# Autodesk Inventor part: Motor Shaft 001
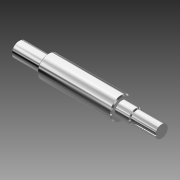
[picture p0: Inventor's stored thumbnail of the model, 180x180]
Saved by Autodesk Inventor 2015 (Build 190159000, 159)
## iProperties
Created: 2007-02
Part Number: Motor Shaft 001
Material: Steel
Document SubType Name: Modeling
Designer: Autodesk, Inc.
Density: 7.85 g/cm^3
Mass: 5212.32 g
Surface Area: 583.464 cm^2
Volume: 663.99 cm^3
Appearance: Chrome - Polished
CustomPartVersion: 1
Author: Autodesk, Inc.
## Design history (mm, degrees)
sketch "Main Sketch"
  geometry: L1 (0, 0)-(368.3, 0) reference; L2 (0, 0)-(0, 19.05); L3 (0, 19.05)-(76.2, 19.05); L4 (76.2, 19.05)-(76.2, 28.575); L5 (266.7, 28.575)-(266.7, 18.415); L6 (76.2, 28.575)-(266.7, 28.575); L7 (304.8, 18.415)-(304.8, 15.875); L8 (266.7, 18.415)-(304.8, 18.415); L9 (368.3, 15.875)-(368.3, 0); L10 (304.8, 15.875)-(368.3, 15.875)
  constraints: 20 end point, 5 vertical, 2 horizontal
  dimensions: "d3" = 38.1 diameter of L3 L1 (derived); "d4" = 57.15 diameter of L6 L1 (derived); "d10" = 36.83 diameter of L8 L1 (derived); "d20" = 31.75 diameter of L10 L1 (derived)
revolve "Revolution1" sketch "Main Sketch" stored, may be unused: angle "d5" = 0 deg
chamfer "Chamfer5" distance "d21" = 2.54; stored, may be unused: second distance "d22" = 3.175, angle "d23" = 45 deg
chamfer "Chamfer2" distance "d11" = 2.54; stored, may be unused: second distance "d12" = 3.175, angle "d13" = 45 deg
chamfer "Chamfer3" distance "d14" = 2.54; stored, may be unused: second distance "d15" = 3.175, angle "d16" = 45 deg
chamfer "Chamfer4" distance "d17" = 2.54; stored, may be unused: second distance "d18" = 3.175, angle "d19" = 45 deg
fillet "Fillet1" dims "d9" = 2.54
feature "Shaft Keyway"
body "Solid1"
other parameters: "d0" = 0, "d1" = 0, "d2" = 0
